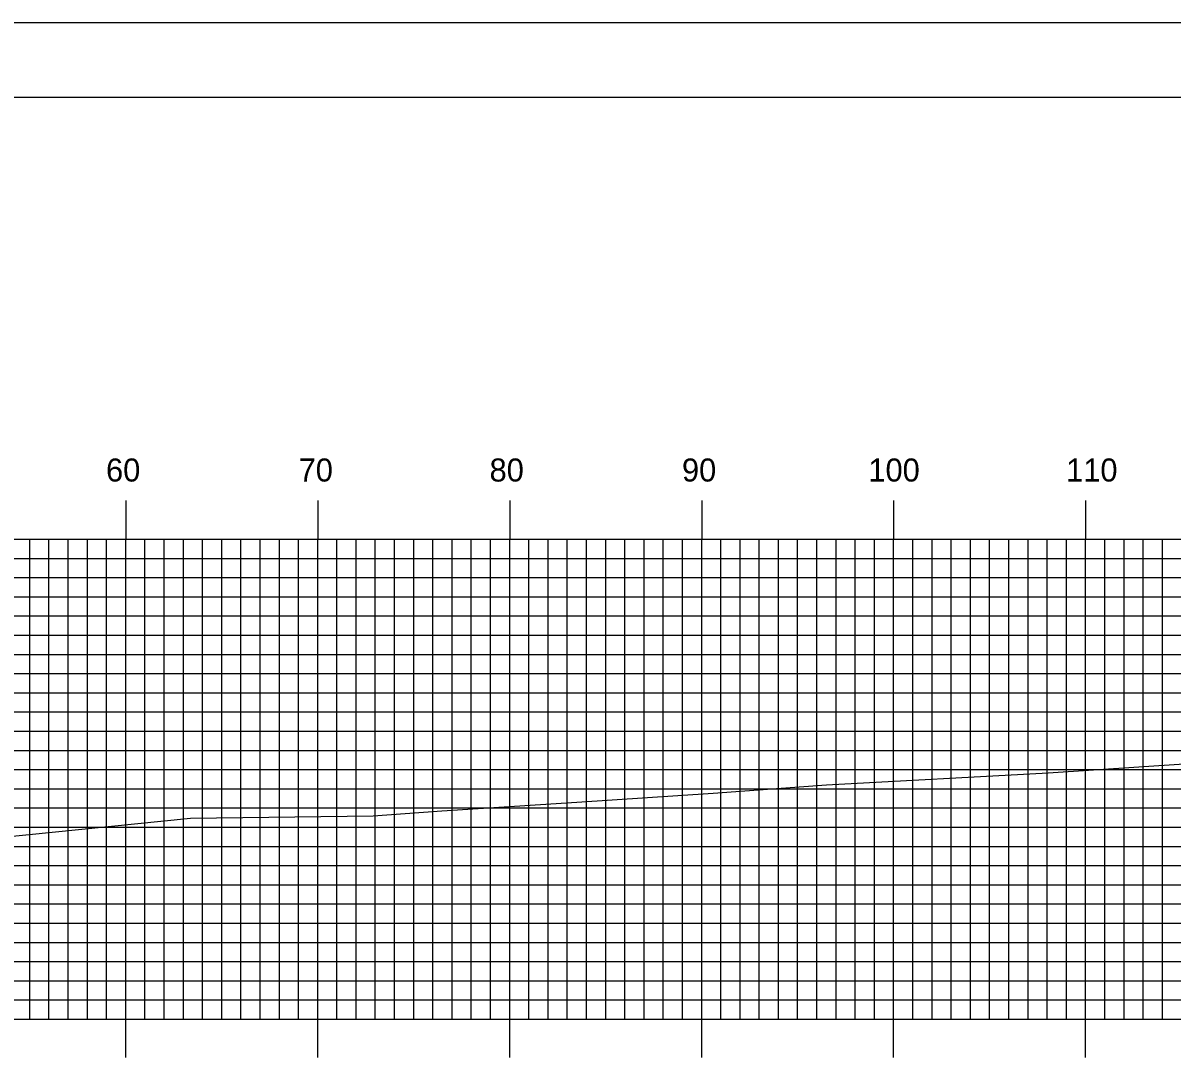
# Model space of a CAD drawing. Extents: x 1763365 to 1763708, y 442591 to 442811.
# Drawn here: x 1763585.5 to 1763645.3, y 442756.2 to 442810.5 of the extents above; entities that cross this region are included whole.
import ezdxf

# ---------------------------------------------------------------- set-up
doc = ezdxf.new("R2010")
doc.units = 0
for name, color, linetype in [('BORDER', 7, 'Continuous'), ('H_V ANNOTATION', 7, 'Continuous'), ('MAJOR', 7, 'Continuous'), ('MINOR', 7, 'Continuous'), ('PLOT BOUNDARY', 7, 'Continuous'), ('S_Roadway_Centerline', 7, 'Continuous')]:
    doc.layers.add(name, color=color, linetype=linetype)

msp = doc.modelspace()

# ---------------------------------------------------------------- linework, layer by layer
at = {"layer": 'BORDER'}
msp.add_lwpolyline([(1763381.205, 442596.665), (1763701.205, 442596.665), (1763701.205, 442806.665), (1763381.205, 442806.665)], close=True, dxfattribs=at)
at = {"layer": 'MAJOR'}
for p, q in [((1763590.805, 442785.669), (1763590.805, 442783.665)), ((1763600.805, 442785.669), (1763600.805, 442783.665)), ((1763610.805, 442785.669), (1763610.805, 442783.665)), ((1763620.805, 442785.669), (1763620.805, 442783.665)), ((1763630.805, 442785.669), (1763630.805, 442783.665)), ((1763640.805, 442785.669), (1763640.805, 442783.665)), ((1763390.805, 442783.665), (1763670.805, 442783.665)), ((1763390.805, 442783.665), (1763670.805, 442783.665)), ((1763590.805, 442758.665), (1763590.805, 442783.665)), ((1763600.805, 442758.665), (1763600.805, 442783.665)), ((1763610.805, 442758.665), (1763610.805, 442783.665)), ((1763620.805, 442758.665), (1763620.805, 442783.665)), ((1763630.805, 442758.665), (1763630.805, 442783.665)), ((1763640.805, 442758.665), (1763640.805, 442783.665)), ((1763390.805, 442778.665), (1763670.805, 442778.665)), ((1763390.805, 442773.665), (1763670.805, 442773.665)), ((1763390.805, 442768.665), (1763670.805, 442768.665)), ((1763390.805, 442763.665), (1763670.805, 442763.665)), ((1763390.805, 442758.665), (1763670.805, 442758.665)), ((1763390.805, 442758.665), (1763670.805, 442758.665)), ((1763590.805, 442756.661), (1763590.805, 442758.665)), ((1763600.805, 442756.661), (1763600.805, 442758.665)), ((1763610.805, 442756.661), (1763610.805, 442758.665)), ((1763620.805, 442756.661), (1763620.805, 442758.665)), ((1763630.805, 442756.661), (1763630.805, 442758.665)), ((1763640.805, 442756.661), (1763640.805, 442758.665))]:
    msp.add_line(p, q, dxfattribs=at)
at = {"layer": 'MINOR'}
for p, q in [((1763585.805, 442758.665), (1763585.805, 442783.665)), ((1763586.805, 442758.665), (1763586.805, 442783.665)), ((1763587.805, 442758.665), (1763587.805, 442783.665)), ((1763588.805, 442758.665), (1763588.805, 442783.665)), ((1763589.805, 442758.665), (1763589.805, 442783.665)), ((1763591.805, 442758.665), (1763591.805, 442783.665)), ((1763592.805, 442758.665), (1763592.805, 442783.665)), ((1763593.805, 442758.665), (1763593.805, 442783.665)), ((1763594.805, 442758.665), (1763594.805, 442783.665)), ((1763595.805, 442758.665), (1763595.805, 442783.665)), ((1763596.805, 442758.665), (1763596.805, 442783.665)), ((1763597.805, 442758.665), (1763597.805, 442783.665)), ((1763598.805, 442758.665), (1763598.805, 442783.665)), ((1763599.805, 442758.665), (1763599.805, 442783.665)), ((1763601.805, 442758.665), (1763601.805, 442783.665)), ((1763602.805, 442758.665), (1763602.805, 442783.665)), ((1763603.805, 442758.665), (1763603.805, 442783.665)), ((1763604.805, 442758.665), (1763604.805, 442783.665)), ((1763605.805, 442758.665), (1763605.805, 442783.665)), ((1763606.805, 442758.665), (1763606.805, 442783.665)), ((1763607.805, 442758.665), (1763607.805, 442783.665)), ((1763608.805, 442758.665), (1763608.805, 442783.665)), ((1763609.805, 442758.665), (1763609.805, 442783.665)), ((1763611.805, 442758.665), (1763611.805, 442783.665)), ((1763612.805, 442758.665), (1763612.805, 442783.665)), ((1763613.805, 442758.665), (1763613.805, 442783.665)), ((1763614.805, 442758.665), (1763614.805, 442783.665)), ((1763615.805, 442758.665), (1763615.805, 442783.665)), ((1763616.805, 442758.665), (1763616.805, 442783.665)), ((1763617.805, 442758.665), (1763617.805, 442783.665)), ((1763618.805, 442758.665), (1763618.805, 442783.665)), ((1763619.805, 442758.665), (1763619.805, 442783.665)), ((1763621.805, 442758.665), (1763621.805, 442783.665)), ((1763622.805, 442758.665), (1763622.805, 442783.665)), ((1763623.805, 442758.665), (1763623.805, 442783.665)), ((1763624.805, 442758.665), (1763624.805, 442783.665)), ((1763625.805, 442758.665), (1763625.805, 442783.665)), ((1763626.805, 442758.665), (1763626.805, 442783.665)), ((1763627.805, 442758.665), (1763627.805, 442783.665)), ((1763628.805, 442758.665), (1763628.805, 442783.665)), ((1763629.805, 442758.665), (1763629.805, 442783.665)), ((1763631.805, 442758.665), (1763631.805, 442783.665)), ((1763632.805, 442758.665), (1763632.805, 442783.665)), ((1763633.805, 442758.665), (1763633.805, 442783.665)), ((1763634.805, 442758.665), (1763634.805, 442783.665)), ((1763635.805, 442758.665), (1763635.805, 442783.665)), ((1763636.805, 442758.665), (1763636.805, 442783.665)), ((1763637.805, 442758.665), (1763637.805, 442783.665)), ((1763638.805, 442758.665), (1763638.805, 442783.665)), ((1763639.805, 442758.665), (1763639.805, 442783.665)), ((1763641.805, 442758.665), (1763641.805, 442783.665)), ((1763642.805, 442758.665), (1763642.805, 442783.665)), ((1763643.805, 442758.665), (1763643.805, 442783.665)), ((1763644.805, 442758.665), (1763644.805, 442783.665)), ((1763390.805, 442782.665), (1763670.805, 442782.665)), ((1763390.805, 442781.665), (1763670.805, 442781.665)), ((1763390.805, 442780.665), (1763670.805, 442780.665)), ((1763390.805, 442779.665), (1763670.805, 442779.665)), ((1763390.805, 442777.665), (1763670.805, 442777.665)), ((1763390.805, 442776.665), (1763670.805, 442776.665)), ((1763390.805, 442775.665), (1763670.805, 442775.665)), ((1763390.805, 442774.665), (1763670.805, 442774.665)), ((1763390.805, 442772.665), (1763670.805, 442772.665)), ((1763390.805, 442771.665), (1763670.805, 442771.665)), ((1763390.805, 442770.665), (1763670.805, 442770.665)), ((1763390.805, 442769.665), (1763670.805, 442769.665)), ((1763390.805, 442767.665), (1763670.805, 442767.665)), ((1763390.805, 442766.665), (1763670.805, 442766.665)), ((1763390.805, 442765.665), (1763670.805, 442765.665)), ((1763390.805, 442764.665), (1763670.805, 442764.665)), ((1763390.805, 442762.665), (1763670.805, 442762.665)), ((1763390.805, 442761.665), (1763670.805, 442761.665)), ((1763390.805, 442760.665), (1763670.805, 442760.665)), ((1763390.805, 442759.665), (1763670.805, 442759.665))]:
    msp.add_line(p, q, dxfattribs=at)
at = {"layer": 'PLOT BOUNDARY'}
msp.add_lwpolyline([(1763365.019, 442590.547), (1763705.019, 442590.547), (1763705.019, 442810.547), (1763365.019, 442810.547)], close=True, dxfattribs=at)
at = {"layer": 'S_Roadway_Centerline'}
msp.add_lwpolyline([(1763572.497, 442766.969), (1763585.608, 442768.272), (1763594.172, 442769.134), (1763603.7, 442769.254), (1763607.273, 442769.512), (1763614.297, 442769.958), (1763621.411, 442770.44), (1763627.303, 442770.86), (1763638.856, 442771.485), (1763653.014, 442772.436), (1763655.412, 442772.579), (1763656.542, 442772.62), (1763669.022, 442773.466), (1763670.805, 442773.481)], dxfattribs=at)

# ---------------------------------------------------------------- texts
at = {"layer": 'H_V ANNOTATION'}
for s, p in [('60', (1763589.778, 442786.665)), ('70', (1763599.81, 442786.665)), ('80', (1763609.756, 442786.665)), ('90', (1763619.778, 442786.665)), ('100', (1763629.489, 442786.665)), ('110', (1763639.789, 442786.665))]:
    msp.add_text(s, height=1.2, dxfattribs=at).set_placement(p)

doc.saveas('drawing.dxf')
